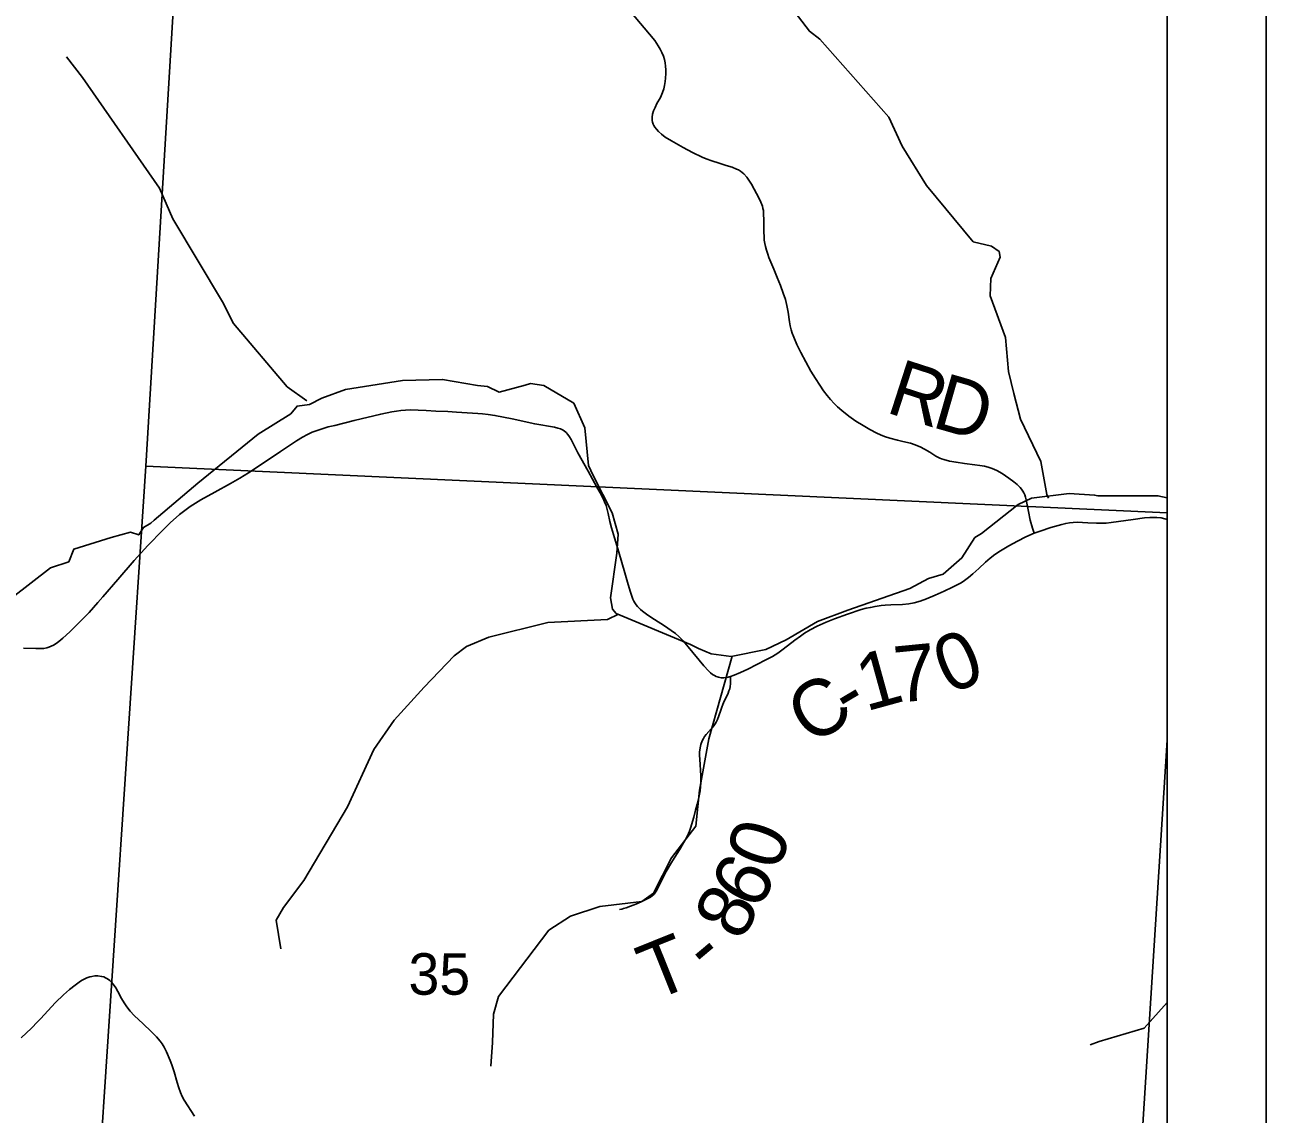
# Model space of a CAD drawing. Extents: x 0 to 34, y 0 to 22.
# Drawn here: x 29.485 to 30.737, y 18.702 to 19.801 of the extents above; entities that cross this region are included whole.
import ezdxf

# ---------------------------------------------------------------- set-up
doc = ezdxf.new("R2010")
doc.units = 0
for name, color, linetype in [('GM_X_County_Road', 7, 'Continuous'), ('GM_X_County_Road_Text', 7, 'Continuous'), ('GM_X_County_Text', 7, 'Continuous'), ('GM_X_Minor_River', 7, 'Continuous'), ('GM_X_Section_Text', 7, 'Continuous'), ('GM_X_State_Shield', 7, 'Continuous'), ('GM_X_Township_Road', 7, 'Continuous'), ('GM_X_Township_Road_Text', 7, 'Continuous'), ('SH_Cut_Line', 7, 'Continuous'), ('SH_Data', 7, 'Continuous')]:
    doc.layers.add(name, color=color, linetype=linetype)

msp = doc.modelspace()

# ---------------------------------------------------------------- linework, layer by layer
at = {"layer": 'GM_X_County_Road'}
for points in [[(30.5032, 19.2885), (30.5015, 19.2937), (30.4992, 19.3018), (30.4974, 19.3104), (30.4951, 19.3224), (30.4945, 19.3249), (30.4937, 19.3272), (30.4927, 19.3293), (30.4917, 19.3311), (30.4905, 19.3329), (30.4891, 19.3346), (30.486, 19.3377), (30.4827, 19.3405), (30.4777, 19.3442), (30.471, 19.3487), (30.4656, 19.3518), (30.461, 19.3539), (30.4589, 19.3546), (30.4569, 19.3553), (30.4532, 19.3561), (30.4483, 19.3568), (30.4434, 19.3576), (30.433, 19.3589), (30.4245, 19.3602), (30.4179, 19.3614), (30.412, 19.3629), (30.4099, 19.3636), (30.408, 19.3644), (30.4042, 19.3664), (30.398, 19.3703), (30.3927, 19.3734), (30.3884, 19.3757), (30.3857, 19.3768), (30.3832, 19.3778), (30.3785, 19.3793), (30.3707, 19.3812), (30.3653, 19.3824), (30.3575, 19.3846), (30.3524, 19.3862), (30.3483, 19.3878), (30.3446, 19.3894), (30.3376, 19.3931), (30.3306, 19.3972), (30.3235, 19.4017), (30.3164, 19.4067), (30.3091, 19.4125), (30.3049, 19.4162), (30.3016, 19.4194), (30.2979, 19.4234), (30.2945, 19.4274), (30.2909, 19.4323), (30.287, 19.4378), (30.2827, 19.4446), (30.2779, 19.4522), (30.2728, 19.4614), (30.2679, 19.471), (30.2639, 19.479), (30.2608, 19.4865), (30.2593, 19.4903), (30.2581, 19.4938), (30.2572, 19.4979), (30.2566, 19.5018), (30.2552, 19.5117), (30.2539, 19.5182), (30.2523, 19.5242), (30.2501, 19.5308), (30.2473, 19.5385), (30.2441, 19.5464), (30.2405, 19.5551), (30.2356, 19.5668), (30.2345, 19.5701), (30.2332, 19.574), (30.2322, 19.5778), (30.2315, 19.581), (30.231, 19.5841), (30.2308, 19.5878), (30.2307, 19.5922), (30.2305, 19.598), (30.2306, 19.6048), (30.2304, 19.6104), (30.2301, 19.6142), (30.2297, 19.6162), (30.2291, 19.6185), (30.2276, 19.6226), (30.2258, 19.6264), (30.2181, 19.6406), (30.2154, 19.6449), (30.2133, 19.6477), (30.2103, 19.6511), (30.2086, 19.6524), (30.207, 19.6538), (30.2049, 19.655), (30.203, 19.656), (30.1987, 19.6577), (30.1925, 19.6597), (30.1855, 19.6619), (30.1781, 19.6642), (30.1724, 19.6662), (30.1684, 19.6679), (30.1585, 19.6727), (30.1491, 19.6776), (30.1373, 19.6843), (30.1312, 19.6882), (30.1273, 19.691), (30.1245, 19.6937), (30.1223, 19.6962), (30.1208, 19.6982), (30.1197, 19.6999), (30.119, 19.7014), (30.1182, 19.7032), (30.1179, 19.7051), (30.1179, 19.7065), (30.1179, 19.7082), (30.1184, 19.7112), (30.1194, 19.7147), (30.1209, 19.7181), (30.1228, 19.722), (30.1262, 19.7282), (30.1284, 19.7332), (30.1296, 19.7368), (30.1304, 19.7404), (30.1311, 19.7442), (30.1315, 19.7476), (30.1317, 19.7525), (30.1317, 19.7562), (30.1314, 19.7596), (30.1309, 19.763), (30.1303, 19.7664), (30.1293, 19.77), (30.1278, 19.7736), (30.1261, 19.7769), (30.1241, 19.7803), (30.1205, 19.7855), (30.1154, 19.792), (30.0919, 19.8201)], [(29.4838, 19.1726), (29.4962, 19.1722), (29.501, 19.1722), (29.5043, 19.1724), (29.5073, 19.173), (29.5095, 19.1737), (29.5117, 19.1746), (29.5141, 19.1758), (29.5168, 19.1774), (29.5197, 19.1794), (29.5235, 19.1826), (29.5305, 19.1891), (29.5393, 19.1977), (29.55, 19.2087), (29.559, 19.2188), (29.5639, 19.2244), (29.5789, 19.2418), (29.5956, 19.261), (29.6093, 19.2762), (29.6244, 19.2918), (29.632, 19.2992), (29.6414, 19.3073), (29.6466, 19.3115), (29.6521, 19.3154), (29.6573, 19.3188), (29.6627, 19.3221), (29.6768, 19.3299), (29.6928, 19.3387), (29.7021, 19.344), (29.7109, 19.3494), (29.7268, 19.36), (29.7431, 19.3709), (29.7592, 19.3817), (29.7654, 19.3854), (29.7702, 19.3881), (29.7751, 19.3905), (29.78, 19.3923), (29.786, 19.3943), (29.7913, 19.3958), (29.798, 19.3974), (29.8174, 19.4022), (29.8442, 19.4087), (29.8554, 19.411), (29.8602, 19.4118), (29.8646, 19.4123), (29.8691, 19.4127), (29.8738, 19.4129), (29.8821, 19.4127), (29.8901, 19.4123), (29.8997, 19.4117), (29.9119, 19.4112), (29.9205, 19.4108), (29.9313, 19.4101), (29.942, 19.4095), (29.9469, 19.4091), (29.9527, 19.4084), (29.9593, 19.4074), (29.9769, 19.4039), (29.9995, 19.3989), (30.0194, 19.3954), (30.0227, 19.3946), (30.0256, 19.3938), (30.0275, 19.3929), (30.0293, 19.3918), (30.0312, 19.3903), (30.033, 19.3882), (30.0347, 19.3857), (30.0364, 19.383), (30.0381, 19.3798), (30.0431, 19.3696), (30.0533, 19.3512), (30.0623, 19.3352), (30.0655, 19.3294), (30.0682, 19.3243), (30.07, 19.3202), (30.0714, 19.3165), (30.0726, 19.3125), (30.0737, 19.3084), (30.0754, 19.3005), (30.0771, 19.2939), (30.08, 19.2838), (30.0844, 19.2693), (30.0904, 19.2487), (30.0938, 19.2369), (30.096, 19.2292), (30.0978, 19.2241), (30.0985, 19.222), (30.0995, 19.2201), (30.1006, 19.2182), (30.1018, 19.2164), (30.103, 19.2148), (30.1045, 19.2132), (30.1061, 19.2116), (30.1082, 19.2099), (30.1137, 19.206), (30.1203, 19.2017), (30.1305, 19.1952), (30.1371, 19.1906), (30.1415, 19.1873), (30.1447, 19.1844), (30.1491, 19.1801), (30.1544, 19.1741), (30.1701, 19.1548), (30.1747, 19.1497), (30.1769, 19.1476), (30.1788, 19.146), (30.1807, 19.1449), (30.1825, 19.144), (30.185, 19.1432), (30.1876, 19.1427), (30.1902, 19.1427), (30.1934, 19.1431), (30.1968, 19.144), (30.2007, 19.1453), (30.2072, 19.1481), (30.2144, 19.1513), (30.2327, 19.1607), (30.2393, 19.1643), (30.2446, 19.1676), (30.2502, 19.1715), (30.262, 19.1807), (30.2674, 19.1848), (30.2715, 19.1876), (30.2772, 19.1911), (30.2843, 19.1949), (30.2934, 19.1989), (30.302, 19.2023), (30.3148, 19.2069), (30.3289, 19.2116), (30.3337, 19.2129), (30.338, 19.2138), (30.3428, 19.2147), (30.3488, 19.2157), (30.3531, 19.2161), (30.3587, 19.2164), (30.3705, 19.2166), (30.3768, 19.2173), (30.3823, 19.2184), (30.3884, 19.2201), (30.3948, 19.2224), (30.4035, 19.2261), (30.4125, 19.2302), (30.421, 19.2341), (30.4263, 19.2368), (30.4295, 19.2386), (30.4329, 19.2409), (30.437, 19.244), (30.4413, 19.2476), (30.4475, 19.253), (30.4543, 19.2594), (30.4588, 19.2633), (30.4637, 19.2671), (30.4694, 19.2708), (30.4776, 19.2758), (30.4864, 19.2806), (30.4949, 19.2848), (30.5032, 19.2885), (30.5093, 19.2908), (30.5201, 19.2944), (30.531, 19.2974), (30.535, 19.2984), (30.5389, 19.2991), (30.5427, 19.2995), (30.5467, 19.2996), (30.5575, 19.2991), (30.5661, 19.2987), (30.5717, 19.2986), (30.576, 19.2988), (30.5809, 19.2993), (30.6032, 19.3025), (30.6145, 19.304), (30.62, 19.3044), (30.6235, 19.3046), (30.627, 19.3045), (30.6312, 19.304), (30.635, 19.3032), (30.6372, 19.3025)], [(29.4817, 18.7794), (29.492, 18.7894), (29.498, 18.7956), (29.501, 18.7987), (29.5162, 18.8151), (29.5243, 18.8229), (29.5304, 18.8283), (29.5359, 18.8328), (29.5399, 18.8357), (29.5425, 18.8373), (29.5452, 18.8387), (29.5479, 18.8399), (29.5508, 18.841), (29.553, 18.8415), (29.5557, 18.8419), (29.5588, 18.842), (29.5627, 18.8415), (29.5648, 18.8409), (29.5667, 18.84), (29.5686, 18.8389), (29.571, 18.8373), (29.5726, 18.8358), (29.5744, 18.8338), (29.5769, 18.8301), (29.5791, 18.8264), (29.5829, 18.8193), (29.5854, 18.8149), (29.5881, 18.8108), (29.5914, 18.8064), (29.5955, 18.8019), (29.6045, 18.7935), (29.6127, 18.7858), (29.618, 18.7804), (29.6217, 18.7761), (29.6237, 18.7735), (29.6259, 18.7701), (29.6283, 18.7654), (29.632, 18.7568), (29.6336, 18.7524), (29.636, 18.7451), (29.6388, 18.7346), (29.6405, 18.729), (29.6422, 18.7243), (29.6441, 18.7203), (29.6461, 18.7166), (29.6563, 18.7004)]]:
    msp.add_lwpolyline(points, dxfattribs=at)
at = {"layer": 'GM_X_County_Text'}
msp.add_lwpolyline([(29.4304, 15.2876), (29.5713, 15.2568), (29.7749, 15.1808), (30.0202, 15.1042), (30.4162, 15.0021), (30.5527, 14.9001), (30.6372, 14.8869), (30.6372, 20.3098), (29.547, 20.3639), (28.6062, 20.4055)], dxfattribs=at)
at = {"layer": 'GM_X_Minor_River'}
for points in [[(30.5176, 19.3238), (30.516, 19.3275), (30.5098, 19.3608), (30.4896, 19.4036), (30.4828, 19.4296), (30.4775, 19.4518), (30.4743, 19.4861), (30.459, 19.528), (30.4595, 19.5454), (30.4689, 19.5671), (30.4679, 19.5729), (30.4601, 19.578), (30.4417, 19.5824), (30.3947, 19.6394), (30.3702, 19.6789), (30.3567, 19.7082), (30.2869, 19.7871), (30.2766, 19.795), (30.2391, 19.8445)], [(29.7697, 19.422), (29.7497, 19.4363), (29.6957, 19.5), (29.6847, 19.5219), (29.6347, 19.6056), (29.6212, 19.6368), (29.5433, 19.7482), (29.5274, 19.7692)], [(30.6372, 19.3242), (30.628, 19.3264), (30.5675, 19.3263), (30.5641, 19.327), (30.5384, 19.3285), (30.5006, 19.3238), (30.487, 19.3177), (30.45, 19.2884), (30.4435, 19.2842), (30.4303, 19.2636), (30.4114, 19.2472), (30.3967, 19.243), (30.3778, 19.2327), (30.3154, 19.2109), (30.2848, 19.1994), (30.2531, 19.1811), (30.2327, 19.1712), (30.1975, 19.1643), (30.1775, 19.1669), (30.1647, 19.1722), (30.1567, 19.1763), (30.0818, 19.2077), (30.078, 19.2119), (30.0758, 19.2233), (30.0822, 19.2685), (30.0836, 19.2875), (30.0776, 19.3092), (30.0586, 19.3468), (30.0537, 19.357), (30.0499, 19.395), (30.0389, 19.4197), (30.0087, 19.4375), (29.9951, 19.4397), (29.9898, 19.4378), (29.9637, 19.4309), (29.952, 19.4366), (29.9418, 19.4377), (29.9066, 19.4437), (29.8661, 19.4425), (29.8087, 19.4336), (29.7849, 19.4248), (29.7724, 19.4183), (29.7599, 19.4168), (29.7535, 19.4091), (29.7207, 19.3885), (29.6598, 19.339), (29.6156, 19.3016), (29.6122, 19.2986), (29.6051, 19.2944), (29.6002, 19.2868), (29.5918, 19.2898), (29.5722, 19.2841), (29.5348, 19.2726), (29.5295, 19.2596), (29.5113, 19.2535), (29.4721, 19.2234)], [(30.0839, 19.2069), (30.073, 19.2015), (30.0127, 19.1985), (29.9531, 19.1837), (29.9307, 19.1743), (29.9182, 19.1649), (29.888, 19.1332), (29.8579, 19.0999), (29.8373, 19.0704), (29.8108, 19.0124), (29.7668, 18.9382), (29.7462, 18.911), (29.7386, 18.8981), (29.7433, 18.8692)], [(30.1987, 19.1645), (30.1751, 19.081), (30.1656, 19.0293), (30.1619, 18.993), (30.1375, 18.9611), (30.1194, 18.9256), (30.1074, 18.9172), (30.0653, 18.9121), (30.0355, 18.9024), (30.0139, 18.888), (29.9631, 18.8212), (29.9581, 18.8035), (29.9568, 18.7747), (29.9553, 18.7509)], [(30.6372, 18.8151), (30.6142, 18.7894), (30.5688, 18.7757), (30.5597, 18.7725)]]:
    msp.add_lwpolyline(points, dxfattribs=at)
at = {"layer": 'GM_X_State_Shield'}
for points in [[(30.6372, 19.3091), (30.6372, 20.318), (29.6678, 20.3647), (29.6072, 19.3563)], [(30.6372, 19.0797), (30.6372, 19.3091), (29.6072, 19.3563), (29.5388, 18.3179), (30.5859, 18.267)], [(30.6372, 18.2643), (30.6372, 19.0797), (30.5859, 18.267)]]:
    msp.add_lwpolyline(points, close=True, dxfattribs=at)
at = {"layer": 'GM_X_Township_Road'}
msp.add_lwpolyline([(30.0851, 18.9091), (30.0872, 18.9094), (30.0892, 18.9099), (30.0917, 18.9107), (30.103, 18.9151), (30.1083, 18.9174), (30.1129, 18.9196), (30.1163, 18.9214), (30.118, 18.9227), (30.1199, 18.9245), (30.122, 18.9274), (30.1251, 18.9332), (30.1272, 18.9373), (30.1312, 18.9455), (30.1341, 18.9506), (30.1366, 18.9548), (30.1401, 18.9606), (30.1438, 18.9664), (30.1467, 18.971), (30.1496, 18.9762), (30.1515, 18.9795), (30.1536, 18.9834), (30.1556, 18.988), (30.1563, 18.99), (30.1569, 18.9921), (30.1576, 18.9944), (30.1599, 19.0022), (30.1618, 19.0092), (30.1633, 19.0151), (30.165, 19.022), (30.1657, 19.0252), (30.1663, 19.0287), (30.1667, 19.0326), (30.1669, 19.0367), (30.1669, 19.0398), (30.167, 19.0437), (30.1661, 19.0605), (30.1658, 19.0643), (30.1658, 19.0677), (30.1663, 19.0721), (30.1671, 19.0756), (30.1683, 19.079), (30.1696, 19.0815), (30.1709, 19.0836), (30.1724, 19.0856), (30.1776, 19.0911), (30.1793, 19.093), (30.1803, 19.0943), (30.1815, 19.0962), (30.1824, 19.0978), (30.1839, 19.1008), (30.1868, 19.1092), (30.1881, 19.113), (30.1892, 19.1159), (30.1906, 19.1191), (30.1932, 19.1242), (30.1945, 19.1271), (30.1954, 19.1295), (30.1962, 19.1316), (30.1966, 19.1339), (30.1968, 19.1365), (30.1968, 19.144)], dxfattribs=at)
at = {"layer": 'SH_Cut_Line'}
msp.add_lwpolyline([(29.4304, 15.2876), (29.5713, 15.2568), (29.7749, 15.1808), (30.0202, 15.1042), (30.4162, 15.0021), (30.5527, 14.9001), (30.6372, 14.8869), (30.6372, 20.9), (23.8372, 20.9)], dxfattribs=at)
at = {"layer": 'SH_Data'}
for points in [[(23.7372, 21), (30.7372, 21), (30.7372, 14), (23.7372, 14)], [(23.8372, 20.9), (30.6372, 20.9), (30.6372, 14.1), (23.8372, 14.1)]]:
    msp.add_lwpolyline(points, close=True, dxfattribs=at)

# ---------------------------------------------------------------- texts
at = {"layer": 'GM_X_County_Road_Text'}
for s, rotation, p in [('R', 342.1118, (30.3522, 19.411)), ('D', 343.9296, (30.3985, 19.3961)), ('0', 22.8253, (30.4175, 19.1254)), ('1', 15.4032, (30.3334, 19.1086)), ('7', 5.6189, (30.3647, 19.1174)), ('C', 32.0401, (30.2778, 19.0736)), ('-', 30.8138, (30.3171, 19.0982))]:
    msp.add_text(s, height=0.0568, rotation=rotation, dxfattribs=at).set_placement(p)
at = {"layer": 'GM_X_Section_Text'}
msp.add_text('35', height=0.04186, rotation=0, dxfattribs=at).set_placement((29.8722, 18.823))
at = {"layer": 'GM_X_Township_Road_Text'}
for s, rotation, p in [('0', 70.935, (30.245, 18.9463)), ('6', 61.4261, (30.2242, 18.9062)), ('8', 62.0232, (30.2078, 18.8754)), ('T', 21.8814, (30.1189, 18.8162)), ('-', 39.982, (30.175, 18.842))]:
    msp.add_text(s, height=0.0568, rotation=rotation, dxfattribs=at).set_placement(p)

doc.saveas('drawing.dxf')
